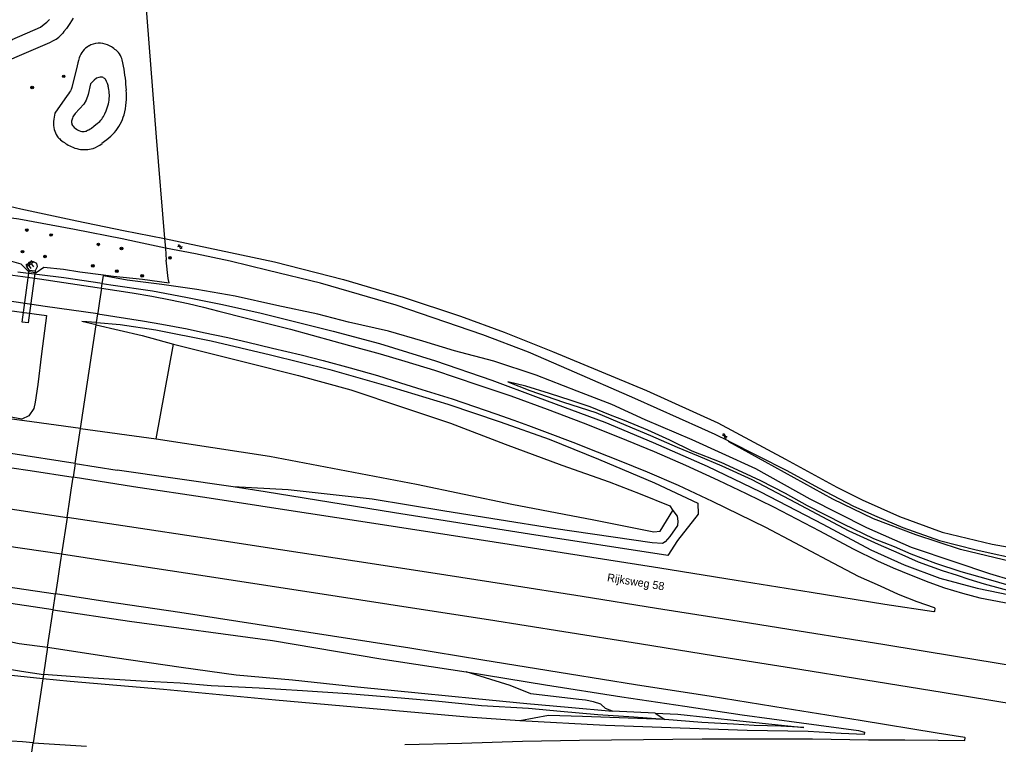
# Model space of a CAD drawing. Extents: x 124000 to 129000, y 395500 to 397503.
# Drawn here: x 124960.5 to 125266.3, y 395834.4 to 396060.7 of the extents above; entities that cross this region are included whole.
import ezdxf

# ---------------------------------------------------------------- set-up
doc = ezdxf.new("R2010")
doc.units = 0
for name, color, linetype in [('gg-afsc-draadraster', 7, 'Continuous'), ('gg-afsc-hekwerk', 7, 'Continuous'), ('gg-afsc-lijn draadraster', 7, 'Continuous'), ('gg-anno-openbare ruimte label', 7, 'Continuous'), ('gg-knt-BGT kruinlijn', 7, 'Continuous'), ('gg-knt-bovenkant onderkant talud', 7, 'Continuous'), ('gg-kntw-bovenkant insteek waterloop', 7, 'Continuous'), ('gg-kntw-waterlijn', 7, 'Continuous'), ('gg-kwrk-faunavoorziening', 7, 'Continuous'), ('gt-grn-vlakafsluiter', 7, 'Continuous'), ('gt-symb-boom', 7, 'Continuous'), ('gt-symb-talud symbool', 7, 'Continuous'), ('gt-symb-watersymbool', 7, 'Continuous'), ('gx-grn-maaiveld', 7, 'Continuous')]:
    doc.layers.add(name, color=color, linetype=linetype)

# ---------------------------------------------------------------- blocks, each defined once
blk = doc.blocks.new('gt0-BOOM')
at = {"layer": 'gt-symb-boom'}
for radius in [0.4, 0.2]:
    blk.add_circle((0, 0), radius, dxfattribs=at)
blk = doc.blocks.new('gt0-WA')
at = {"layer": 'gt-symb-watersymbool'}
for centre, start, end in [((-0.32, 0.02), 28.0725, 151.9275), ((0.43, 0.42), 208.0725, 331.9275), ((-0.32, -0.43), 28.0725, 151.9275), ((0.43, -0.03), 208.0725, 331.9275)]:
    blk.add_arc(centre, 0.425, start, end, dxfattribs=at)
blk = doc.blocks.new('gt0-TALUD_1')
at = {"layer": 'gt-symb-talud symbool'}
for p, q in [((-1, -1), (-1, 0)), ((-0.5, -2), (-0.5, 0)), ((0, -1), (0, 0)), ((0.5, -2), (0.5, 0)), ((1, -1), (1, 0))]:
    blk.add_line(p, q, dxfattribs=at)

msp = doc.modelspace()

# ---------------------------------------------------------------- linework, layer by layer
at = {"layer": 'gg-afsc-draadraster'}
for p, q in [((125005.78, 395992.35), (125006.06, 395989.36)), ((125006.06, 395989.36), (125006.27, 395985.6)), ((124963.48, 395982.03), (124965.35, 395981.77))]:
    msp.add_line(p, q, dxfattribs=at)
for points in [[(124994.79, 396132.83), (124999.73, 396068.16), (125003.22, 396023.97), (125005.78, 395992.35)], [(124948.39, 395987.53), (124951.71, 395986.77), (124957.98, 395985.27), (124960.92, 395984.49), (124963.25, 395982.06), (124963.48, 395982.03)], [(124965.35, 395981.77), (124965.64, 395981.73), (124968.12, 395983.39), (124974.24, 395982.8), (124979.37, 395981.96), (124986.74, 395981.02)], [(124986.74, 395981.02), (124989.87, 395980.62), (124998.89, 395979.66), (125007.19, 395978.48), (125006.97, 395979.93)]]:
    msp.add_lwpolyline(points, dxfattribs=at)
at = {"layer": 'gg-afsc-hekwerk'}
msp.add_line((125006.97, 395979.93), (125006.27, 395985.6), dxfattribs=at)
at = {"layer": 'gg-afsc-lijn draadraster'}
msp.add_line((125005.78, 395992.35), (125006.06, 395989.36), dxfattribs=at)
msp.add_lwpolyline([(124948.99, 395941.01), (124950.28, 395952.41), (124949.95, 395955.35), (124949.11, 395957.86), (124947.84, 395960.85), (124946.88, 395963.53), (124946.99, 395966.25), (124947.68, 395968.09), (124949.91, 395969.27), (124951.83, 395970.66), (124968.93, 395968.34), (124967.37, 395956.39), (124966.16, 395946.77), (124965.39, 395941.28), (124964.92, 395939.34), (124963.38, 395936.98), (124961.16, 395935.92), (124949.83, 395937.99)], dxfattribs=at)
at = {"layer": 'gg-knt-BGT kruinlijn'}
for p, q in [((124974.31, 395980.05), (124959.98, 395981.83)), ((124986.34, 395978.29), (124974.31, 395980.05)), ((124986.34, 395978.29), (124989.01, 395977.89)), ((124989.01, 395977.89), (125002.05, 395976.06)), ((125002.05, 395976.06), (125012.49, 395974.02)), ((125012.49, 395974.02), (125023.92, 395971.77)), ((125023.92, 395971.77), (125035.97, 395969.02)), ((124984.5, 395966.11), (124979.99, 395966.47)), ((124984.5, 395966.11), (124991.95, 395965.53)), ((125035.97, 395969.02), (125058.52, 395963.47)), ((124991.95, 395965.53), (125003.05, 395963.86)), ((125003.05, 395963.86), (125020.32, 395960.41)), ((125058.52, 395963.47), (125072.94, 395959.6)), ((125020.32, 395960.41), (125038.86, 395956.02)), ((125072.94, 395959.6), (125090.47, 395954.22)), ((125038.86, 395956.02), (125057.49, 395951.45)), ((125090.47, 395954.22), (125108.04, 395948.1)), ((125057.49, 395951.45), (125077.12, 395945.87)), ((125108.04, 395948.1), (125122.48, 395942.75)), ((125077.12, 395945.87), (125094.28, 395940.61)), ((125122.48, 395942.75), (125143.34, 395934.99)), ((125094.28, 395940.61), (125110.71, 395935.1)), ((125110.71, 395935.1), (125125.95, 395929.74)), ((125143.34, 395934.99), (125158.48, 395928.65)), ((125125.95, 395929.74), (125141.39, 395923.49)), ((125158.48, 395928.65), (125175.33, 395921.32)), ((124977.87, 395922.08), (124957.82, 395925.21)), ((125141.39, 395923.49), (125158.9, 395916.09)), ((124977.87, 395922.08), (124990.97, 395920.04)), ((125175.33, 395921.32), (125192.01, 395913.28)), ((125214.63, 395911.02), (125193.47, 395922.66)), ((125027.2, 395914.82), (124990.97, 395920.04)), ((125037.2, 395913.28), (125027.2, 395914.82)), ((125158.9, 395916.09), (125172.46, 395909.78)), ((125077.63, 395906.76), (125037.2, 395913.28)), ((125192.01, 395913.28), (125211.5, 395903.15)), ((125227.26, 395904.81), (125214.63, 395911.02)), ((125172.46, 395909.78), (125172.53, 395906.31)), ((125119.79, 395900.08), (125077.63, 395906.76)), ((125172.53, 395906.31), (125166.1, 395898.04)), ((125211.5, 395903.15), (125226.47, 395895.14)), ((125240.55, 395899.8), (125227.26, 395904.81)), ((125163.09, 395893.43), (125119.79, 395900.08)), ((125254.46, 395895.24), (125240.55, 395899.8)), ((125166.1, 395898.04), (125163.09, 395893.43)), ((125226.47, 395895.14), (125236.84, 395890.43)), ((125270.51, 395891.41), (125254.46, 395895.24)), ((125236.84, 395890.43), (125248.04, 395886.3)), ((125248.04, 395886.3), (125259.66, 395883.23)), ((125259.66, 395883.23), (125280.39, 395878.85)), ((124970.99, 395876.42), (124949.46, 395879.62)), ((124970.99, 395876.42), (124994.89, 395872.87)), ((124994.89, 395872.87), (125039.54, 395866.8)), ((125039.54, 395866.8), (125073.33, 395861.13)), ((125073.33, 395861.13), (125100.01, 395857.02)), ((125100.01, 395857.02), (125124.84, 395853.03)), ((124967.75, 395854.92), (124958.03, 395855.88)), ((124976.29, 395854.07), (124967.75, 395854.92)), ((125005.5, 395851.54), (124976.29, 395854.07)), ((125124.84, 395853.03), (125148.66, 395849.3)), ((125040.44, 395848.26), (125005.5, 395851.54)), ((125069.83, 395845.64), (125040.44, 395848.26)), ((125148.66, 395849.3), (125168.4, 395846.37)), ((125100.42, 395842.92), (125069.83, 395845.64)), ((125168.4, 395846.37), (125186.25, 395843.67)), ((125186.25, 395843.67), (125204.76, 395841.13)), ((125116.76, 395841.72), (125100.42, 395842.92)), ((125143.62, 395840.27), (125116.76, 395841.72)), ((125204.76, 395841.13), (125222.64, 395838.75)), ((125166.93, 395839.48), (125143.62, 395840.27)), ((125187.81, 395838.8), (125166.93, 395839.48)), ((125206.94, 395838.44), (125187.81, 395838.8)), ((125217.21, 395837.86), (125206.94, 395838.44)), ((125224.43, 395837.52), (125217.21, 395837.86)), ((125222.64, 395838.75), (125224.53, 395838.21)), ((125224.53, 395838.21), (125224.43, 395837.52))]:
    msp.add_line(p, q, dxfattribs=at)
at = {"layer": 'gg-knt-bovenkant onderkant talud'}
msp.add_line((124965.41, 395982.16), (124963.54, 395982.39), dxfattribs=at)
msp.add_lwpolyline([(124965.41, 395982.16), (124966.08, 395983.6), (124965.85, 395984.58), (124964.67, 395985.16), (124963.35, 395984.9), (124962.59, 395983.78), (124963.46, 395982.41), (124963.54, 395982.39)], dxfattribs=at)
at = {"layer": 'gg-kntw-bovenkant insteek waterloop'}
for points in [[(124977.21, 396061.12), (124976.73, 396060.31), (124976.23, 396059.52), (124975.15, 396057.96), (124974.38, 396056.96), (124973.98, 396056.48), (124973.56, 396056.02)], [(124944.57, 395987.79), (124947.03, 395995.16), (124949.13, 396002.91), (124951.13, 396012.24), (124953.24, 396024.65), (124954.34, 396044.56), (124954.54, 396046.35), (124955.22, 396047.11), (124959.02, 396048.86), (124969.99, 396053.61), (124971.11, 396054.17), (124971.91, 396054.64)], [(124979.16, 396048.76), (124978.92, 396048), (124978.73, 396047.23), (124978.31, 396045.36), (124977.33, 396041.67), (124976.81, 396039.48), (124976.72, 396039.18), (124976.6, 396038.89), (124976.38, 396038.47), (124976.12, 396038.07), (124975.74, 396037.55), (124975.33, 396037.05), (124971.5, 396031.47), (124971.27, 396030.22), (124971.18, 396029.58), (124971.12, 396028.95)], [(124992.97, 396046.23), (124992.79, 396047.18), (124992.57, 396048.11), (124992.44, 396048.57), (124992.27, 396049.02)], [(124987.79, 396023.23), (124987.03, 396022.61), (124986.25, 396022.02)], [(125006.06, 395989.36), (124997.34, 395991.23), (124992.6, 395992.31), (124977.66, 395995.2), (124960.23, 395998.44), (124954.95, 395999.18), (124954.32, 396000.53), (124954.62, 396002.44), (124955.62, 396002.85), (124960.93, 396001.63), (124978.41, 395997.9), (124992.95, 395994.88), (125005.78, 395992.35)], [(125005.78, 395992.35), (125040.2, 395985.07), (125061.72, 395979.62), (125080.39, 395974.01), (125098.23, 395968.13), (125111.87, 395963.14), (125126.99, 395957.11), (125156.35, 395944.96), (125178.62, 395934.82), (125199.79, 395923.5), (125215.85, 395914.77), (125223.8, 395910.78), (125235.44, 395905.57), (125248.8, 395900.71), (125264.33, 395896.93), (125285.59, 395893.17), (125313.16, 395887.92), (125321.47, 395886.43)]]:
    msp.add_lwpolyline(points, dxfattribs=at)
for centre, radius, start, end in [((124967.04, 396062.14), 8.94, 302.9785, 316.8031), ((124985.7, 396046.6), 6.9, 121.5264, 161.6793), ((124985.37, 396046.97), 6.4, 65.7908, 120.712), ((124984.12, 396043.67), 9.93, 46.1953, 67.0265), ((124986.86, 396046.57), 5.94, 24.3076, 45.8623), ((124938.01, 396035.95), 55.92, 2.7576, 10.592), ((124964.13, 396036.98), 29.77, 355.8219, 3.1898), ((124974.24, 396036.3), 19.64, 344.3408, 355.6706), ((124979.05, 396034.96), 14.65, 331.7878, 344.3029), ((124979.39, 396028.33), 8.29, 175.6837, 193.6302), ((124980.29, 396034.45), 13.31, 317.5715, 331.2056), ((124976.99, 396027.7), 5.81, 193.2026, 215.3279), ((124977.77, 396028.45), 6.88, 216.6343, 229.8974), ((124972.63, 396041.33), 23.61, 309.9524, 317.7873), ((124983.28, 396035.17), 15.57, 230.3099, 244.5496), ((124981.2, 396030.87), 10.8, 244.7253, 258.2912), ((124979.89, 396030.58), 10.68, 289.4526, 306.6204), ((124980.82, 396028.66), 8.55, 257.818, 287.8694)]:
    msp.add_arc(centre, radius, start, end, dxfattribs=at)
at = {"layer": 'gg-kntw-waterlijn'}
msp.add_line((124977.21, 396027.42), (124977.55, 396027.06), dxfattribs=at)
for points in [[(124942.96, 395987.76), (124942.42, 395988.9), (124941.62, 395990.01), (124942.61, 395994.4), (124944.51, 395999.91), (124946.3, 396003.69), (124947.34, 396007.43), (124949.35, 396019.66), (124950.9, 396038.47), (124951.93, 396048.84), (124952.63, 396049.9), (124954.38, 396051.6), (124958.15, 396054.47), (124966.99, 396058.38), (124968.19, 396059.26)], [(124985.69, 396042.75), (124985.22, 396042.64), (124984.52, 396042.39), (124983.76, 396041.76), (124982.69, 396040.65), (124981.92, 396037.34), (124981.3, 396035.53), (124980.59, 396034.33), (124977.89, 396031.44), (124977.35, 396030.63), (124977.17, 396030.31), (124977.01, 396029.98)], [(124986.66, 396042.64), (124986.88, 396042.53), (124987.06, 396042.38), (124987.22, 396042.2), (124987.35, 396042), (124987.57, 396041.54), (124987.84, 396040.83), (124988.14, 396039.9)], [(124987.19, 396031.33), (124987.59, 396032.24), (124987.92, 396033.17)], [(124984.83, 396028.27), (124983.7, 396027.34), (124982.93, 396026.74), (124982.52, 396026.47), (124982.1, 396026.23), (124981.76, 396026.07), (124981.42, 396025.93)], [(124979.04, 396026.1), (124979.51, 396025.93), (124979.99, 396025.81)]]:
    msp.add_lwpolyline(points, dxfattribs=at)
for centre, radius, start, end in [((124959.84, 396070.42), 13.94, 306.8207, 315.9123), ((124985.98, 396040.84), 1.93, 69.235, 98.5006), ((124978.53, 396037.04), 10.03, 351.7256, 16.5855), ((124973.95, 396037.55), 14.64, 342.5926, 352.3147), ((124978.87, 396035.3), 9.22, 310.2934, 334.5026), ((124979.94, 396028.71), 3.19, 156.5737, 181.2518), ((124978.69, 396028.67), 1.94, 180.9219, 220.149), ((124981.37, 396031.34), 5.74, 228.1781, 246.0305), ((124980.47, 396028.7), 2.93, 260.5988, 288.9881)]:
    msp.add_arc(centre, radius, start, end, dxfattribs=at)
at = {"layer": 'gg-kwrk-faunavoorziening'}
msp.add_lwpolyline([(124965.41, 395982.16), (124963.16, 395966.02), (124961.29, 395966.23), (124963.54, 395982.39)], dxfattribs=at)
at = {"layer": 'gt-grn-vlakafsluiter'}
msp.add_line((124986.71, 395980.76), (124986.74, 395981.02), dxfattribs=at)
at = {"layer": 'gx-grn-maaiveld'}
for p, q in [((124986.12, 395976.86), (124986.34, 395978.29)), ((124986.34, 395978.29), (124986.71, 395980.76)), ((124984.4, 395965.43), (124979.99, 395966.47)), ((124984.4, 395965.43), (124984.5, 395966.11)), ((124984.5, 395966.11), (124984.92, 395968.87)), ((124979.53, 395933.08), (124984.4, 395965.43)), ((125003.23, 395929.86), (125008.56, 395959.42)), ((124977.87, 395922.08), (124979.53, 395933.08)), ((124979.53, 395933.08), (125003.23, 395929.86)), ((125182.14, 395929.05), (125177.88, 395931.2)), ((124977.87, 395922.08), (124977.23, 395917.8)), ((124975.33, 395905.21), (124973.6, 395893.76)), ((124970.99, 395876.42), (124971.74, 395881.4)), ((124969.23, 395864.73), (124970.99, 395876.42)), ((124969.23, 395864.73), (124967.96, 395856.27)), ((124967.96, 395856.27), (124967.75, 395854.92)), ((124967.75, 395854.92), (124964.73, 395834.85)), ((125159.13, 395844.18), (125145.73, 395844.77)), ((125159.13, 395844.18), (125162.15, 395842.23))]:
    msp.add_line(p, q, dxfattribs=at)
for points in [[(124932.45, 395991.7), (124932.68, 395991.15), (124933.94, 395989.09), (124935.37, 395987.32), (124937.14, 395985.64), (124939.42, 395984.3), (124941.19, 395983.5), (124943.68, 395982.89), (124947.83, 395982.25), (124955.27, 395981.32), (124961.57, 395980.53), (124966.68, 395979.79), (124974.31, 395978.62), (124984.74, 395977.07), (124986.12, 395976.86)], [(125177.88, 395931.2), (125173.69, 395933.08), (125152.76, 395942.46), (125132.17, 395951.33), (125119.48, 395956.83), (125105.2, 395962.3), (125078.15, 395971.59), (125063.48, 395975.82), (125054.5, 395978.4), (125038.21, 395982.42), (125026.3, 395985.26), (125015.48, 395987.54), (125006.06, 395989.36)], [(125270.67, 395885.59), (125263.67, 395887.64), (125252.77, 395891.31), (125239.2, 395895.9), (125225.2, 395901.99), (125207.48, 395910.95), (125190.59, 395920.41), (125180.07, 395925.22), (125170.67, 395929.54), (125155.93, 395935.8), (125145.57, 395940.52), (125134.67, 395944.73), (125121.87, 395949.67), (125108.65, 395954.04), (125096.4, 395957.29), (125086.51, 395960.27), (125075.76, 395963.44), (125063.31, 395966.25), (125053.71, 395968.73), (125040.88, 395971.47), (125027.86, 395974.32), (125015.84, 395976.43), (125004.98, 395977.97), (124994.1, 395979.38), (124986.71, 395980.76)], [(124984.92, 395968.87), (124968.45, 395971.18), (124950.3, 395973.85), (124940.31, 395975.32), (124933.58, 395976.12)], [(124986.12, 395976.86), (124985.5, 395972.76), (124984.96, 395969.16), (124984.92, 395968.87)], [(124986.12, 395976.86), (124995.63, 395975.42), (125001.83, 395974.37), (125007.66, 395973.24), (125013.13, 395972.08), (125017.96, 395970.95), (125022.78, 395969.68), (125031.39, 395967.47), (125045.13, 395964.01), (125058.66, 395960.32), (125063.63, 395958.99), (125073.21, 395956.31), (125080.89, 395954.06), (125090.11, 395951.22), (125103.65, 395946.71), (125113.95, 395943.22), (125125.31, 395939.11), (125136.6, 395934.77), (125147.87, 395930.39), (125158.81, 395925.85), (125168.53, 395921.59), (125178.74, 395916.96), (125187.53, 395912.76), (125196.08, 395908.55), (125210.39, 395901.11), (125220.99, 395895.44), (125228.52, 395891.73), (125233.49, 395889.56), (125239.03, 395887.22), (125244.55, 395885.07), (125249.46, 395883.32), (125255.06, 395881.59), (125260.57, 395880.16), (125279.81, 395876.48)], [(124984.92, 395968.87), (124998.86, 395966.7), (125004.98, 395965.64), (125012.86, 395964.12), (125017.96, 395963.04), (125025.56, 395961.43), (125031.86, 395959.99), (125039.48, 395958.17), (125048.45, 395956.03), (125055.32, 395954.25), (125063.82, 395952.02), (125072.32, 395949.64), (125079.54, 395947.3), (125086.15, 395945.27), (125095.62, 395942.31), (125102.63, 395939.94), (125109.27, 395937.6), (125114.93, 395935.61), (125119.55, 395933.99), (125125.39, 395931.83), (125133.34, 395928.73), (125140.93, 395925.73), (125147.81, 395923.04), (125156.54, 395919.47), (125166.23, 395915.32), (125176.87, 395910.34), (125185.28, 395906.29), (125193.55, 395902.23), (125202.67, 395897.43), (125212.81, 395891.99), (125222.55, 395886.94), (125229.35, 395883.88), (125235.03, 395881.33), (125240.83, 395879.01), (125246.24, 395877.12), (125246.45, 395876.95), (125246.32, 395875.89), (125246.18, 395875.82), (125230.84, 395878.08), (125207.81, 395881.8), (125184.39, 395885.55), (125160.54, 395889.47), (125137.34, 395893.1), (125113.51, 395896.84), (125090.05, 395900.49), (125067.08, 395904.01), (125043.26, 395907.68), (125019.74, 395911.27), (124996.13, 395914.87), (124977.23, 395917.8)], [(124984.4, 395965.43), (124998.82, 395962.04), (125008.56, 395959.42)], [(125008.56, 395959.42), (125031.51, 395953.63), (125047.62, 395949.56), (125063.95, 395945.17), (125080.15, 395939.72), (125095.12, 395934.74), (125112.26, 395928.16), (125129.91, 395921.59), (125144.74, 395916.4), (125154.43, 395912.65), (125163.66, 395908.9), (125164.61, 395907.49)], [(125272.95, 395883.1), (125263.21, 395885.88), (125254.69, 395888.33), (125246.76, 395890.91), (125239.11, 395893.85), (125233.84, 395896.1), (125227.38, 395898.56), (125217.89, 395903.13), (125206.67, 395908.85), (125199.79, 395912.76), (125192.15, 395916.69), (125186.28, 395919.39), (125179.69, 395922.42), (125170.66, 395926.01), (125163.62, 395929.38), (125156.79, 395932.55), (125149.46, 395935.51), (125145.13, 395937.2), (125138.78, 395939.79), (125132.84, 395941.75), (125126.09, 395944.02), (125118.69, 395946.27), (125113.04, 395947.66), (125119.94, 395944.89), (125130.4, 395941.29), (125140.53, 395938.05), (125149.9, 395934.04), (125157.65, 395930.84), (125165.98, 395927.21), (125172.52, 395924.5), (125179.88, 395921.42), (125189.33, 395917.16), (125202.98, 395909.94), (125219.59, 395901.11), (125228.79, 395896.92), (125235.21, 395894.09), (125241.29, 395891.45), (125248.76, 395888.74), (125253.48, 395887.23), (125257.04, 395885.99), (125261.89, 395884.54), (125270.75, 395882.13)], [(124979.53, 395933.08), (124962.09, 395935.45), (124936.69, 395938.79), (124934.12, 395937.79), (124932.14, 395936.66)], [(125003.23, 395929.86), (125038.56, 395924.38), (125084.53, 395915.67), (125114.28, 395909.45), (125139.88, 395904.48), (125158.66, 395900.76), (125160.64, 395900.94), (125164.61, 395907.49)], [(124938.01, 395927.23), (124941.28, 395926.72), (124941.09, 395925.35), (124940.82, 395923.3), (124963.82, 395919.89), (124977.23, 395917.8)], [(125193.47, 395922.66), (125182.06, 395928.91), (125182.14, 395929.05)], [(125182.14, 395929.05), (125200.23, 395919.89), (125210.15, 395914.48), (125221.04, 395908.8), (125228.32, 395905.52), (125236.43, 395902.09), (125247.89, 395898.09), (125259.35, 395895.13), (125274.45, 395891.85), (125320.47, 395883.44), (125342.15, 395879.12), (125348.01, 395877.54)], [(124975.33, 395905.21), (124975.55, 395906.66), (124976.08, 395910.19), (124976.62, 395913.8), (124977.23, 395917.8)], [(125164.61, 395907.49), (125165.98, 395905.67), (125166.17, 395904.06), (125166.04, 395902.71), (125163.69, 395899.3), (125162.2, 395897.66), (125161.39, 395897.13), (125158.18, 395897.36), (125127.31, 395901.83), (125093.38, 395907.23), (125070.68, 395910.96), (125044.44, 395913.94), (125027.2, 395914.82)], [(124935.6, 395910.58), (124935.93, 395911.01), (124949.98, 395909.07), (124975.33, 395905.21)], [(125345.82, 395846.55), (125323.91, 395850.19), (125300.7, 395854.01), (125277.13, 395857.87), (125253.53, 395861.71), (125230.25, 395865.59), (125206.64, 395869.34), (125182.72, 395873.18), (125159.55, 395876.88), (125136.27, 395880.54), (125112.39, 395884.37), (125088.98, 395887.95), (125065.28, 395891.6), (125042.05, 395895.12), (125018.31, 395898.85), (124994.8, 395902.29), (124975.33, 395905.21)], [(124973.6, 395893.76), (124955.69, 395896.43), (124934.3, 395899.72), (124933.94, 395899.8)], [(124973.6, 395893.76), (124973.43, 395892.61), (124972.9, 395889.1), (124972.35, 395885.43), (124971.74, 395881.4)], [(125344.98, 395834.66), (125319.02, 395839.09), (125296.05, 395842.77), (125272.24, 395846.79), (125248.73, 395850.65), (125224.92, 395854.46), (125201.72, 395858.18), (125177.96, 395861.98), (125154.17, 395865.81), (125130.6, 395869.55), (125107.04, 395873.28), (125083.26, 395876.94), (125059.73, 395880.58), (125036.04, 395884.26), (125012.39, 395887.88), (124988.38, 395891.49), (124973.6, 395893.76)], [(124931.61, 395883.85), (124934.74, 395883.48), (124934.97, 395884.68), (124936.49, 395886.62), (124949.78, 395884.68), (124971.74, 395881.4)], [(125080.89, 395834.33), (125098.73, 395834.84), (125117.62, 395835.42), (125135.41, 395835.73), (125155.48, 395835.93), (125173.81, 395836.1), (125190.63, 395836.19), (125208.29, 395836.16), (125225.71, 395835.87), (125237.1, 395835.8), (125247.53, 395835.69), (125255.69, 395835.58), (125255.83, 395835.69), (125255.93, 395836.45), (125255.84, 395836.54), (125247.16, 395837.91), (125223.09, 395841.91), (125199.68, 395845.62), (125176.61, 395849.32), (125152.96, 395853.04), (125132.33, 395856.36), (125105.29, 395860.67), (125082.46, 395864.45), (125058.26, 395868.23), (125034.7, 395871.86), (125010.59, 395875.63), (124987.09, 395879.07), (124971.74, 395881.4)], [(124925.46, 395876.02), (124930.33, 395872.83), (124940.4, 395870.92), (124946.11, 395869.75), (124953.31, 395867.35), (124960.36, 395865.92), (124969.23, 395864.73)], [(124969.23, 395864.73), (124990.25, 395861.54), (125011.02, 395858.54), (125028.16, 395856.1), (125045.73, 395854.53), (125066.13, 395852.37), (125086.07, 395850.43), (125102.96, 395848.74), (125119.03, 395847.16), (125131.95, 395846.08), (125145.73, 395844.77)], [(124951.79, 395857.24), (124954.77, 395858.31), (124961.12, 395857.32), (124967.96, 395856.27)], [(125162.15, 395842.23), (125152.43, 395842.95), (125141.19, 395843.69), (125129.56, 395844.65), (125119.46, 395845.64), (125104.83, 395846.41), (125090.47, 395847.88), (125079.68, 395848.85), (125063.03, 395850.19), (125048.92, 395851.14), (125035.36, 395851.96), (125020.37, 395852.7), (125010.69, 395853.58), (124998.51, 395854.19), (124983.45, 395855.04), (124967.96, 395856.27)], [(125145.73, 395844.77), (125143.58, 395845.58), (125142.06, 395846.93), (125139.84, 395847.66), (125137.36, 395848.18), (125135.22, 395848.44), (125120.26, 395850.22), (125113.79, 395852.79), (125100.01, 395857.02)], [(125159.13, 395844.18), (125166.15, 395843.84), (125185.59, 395841.72), (125205.49, 395839.66), (125198.34, 395840.1), (125190.05, 395840.28), (125183.55, 395840.68), (125173.68, 395841.25), (125162.15, 395842.23)], [(125162.15, 395842.23), (125136.43, 395843.17), (125125.76, 395843.44), (125116.76, 395841.72)], [(124964.73, 395834.85), (124961.38, 395835.19), (124954.59, 395835.65), (124934.77, 395837.49)], [(124963.6, 395827.36), (124964.08, 395830.55), (124964.62, 395834.16), (124964.73, 395834.85)], [(124964.73, 395834.85), (124981.42, 395833.89)]]:
    msp.add_lwpolyline(points, dxfattribs=at)

# ---------------------------------------------------------------- block references
at = {"layer": 'gt-symb-boom'}
for p in [(124974.29, 396042.99), (124964.44, 396039.51), (124962.75, 395995), (124970.35, 395993.45), (124985.12, 395990.53), (124961.43, 395988.25), (124992.33, 395989.23), (124968.46, 395986.74), (125007.5, 395986.34), (124983.4, 395983.85), (124990.9, 395982.18), (124998.8, 395980.73)]:
    msp.add_blockref('gt0-BOOM', p, dxfattribs=at)
at = {"layer": 'gt-symb-talud symbool', "xscale": 0.9999699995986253, "yscale": 0.9999699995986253, "rotation": 35.31121343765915}
msp.add_blockref('gt0-TALUD_1', (124963.35, 395984.9), dxfattribs=at)
at = {"layer": 'gt-symb-watersymbool'}
for p, rotation in [((125010.57, 395989.83), -11.950647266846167), ((125180.76, 395930.74), -25.92418551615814)]:
    msp.add_blockref('gt0-WA', p, dxfattribs=dict(at, rotation=rotation))

# ---------------------------------------------------------------- texts
at = {"layer": 'gg-anno-openbare ruimte label'}
msp.add_text('Rijksweg 58', height=2.5, rotation=350.8, dxfattribs=at).set_placement((125143.95, 395885.37))

doc.saveas('drawing.dxf')
